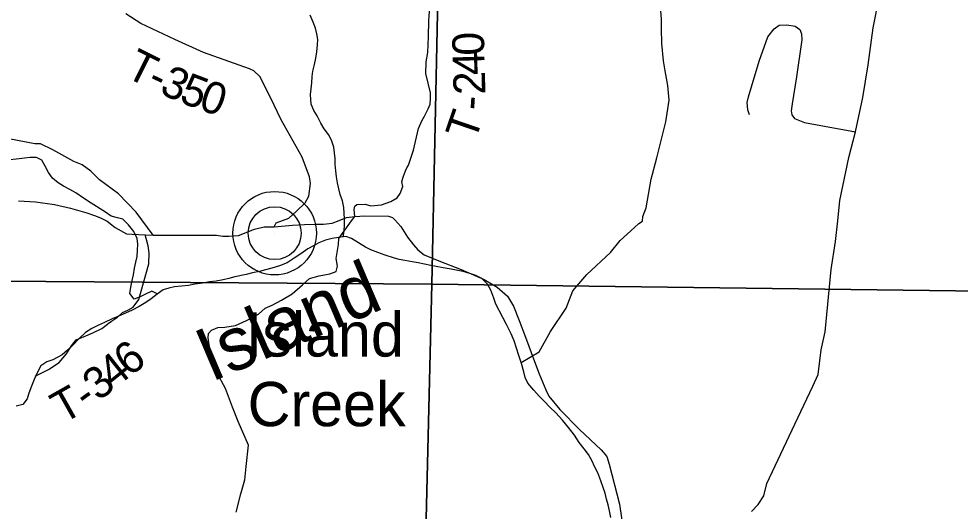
# Model space of a CAD drawing. Extents: x 2.1 to 8.9, y 14.1 to 20.9.
# Drawn here: x 3.78 to 5.459, y 17.71 to 18.588 of the extents above; entities that cross this region are included whole.
import ezdxf

# ---------------------------------------------------------------- set-up
doc = ezdxf.new("R2010")
doc.units = 0
for name, color, linetype in [('GM_X_City_Street', 7, 'Continuous'), ('GM_X_Interchange_Ramps', 7, 'Continuous'), ('GM_X_Major_River', 7, 'Continuous'), ('GM_X_Minor_River_Text', 7, 'Continuous'), ('GM_X_Rail_Line_Text', 7, 'Continuous'), ('GM_X_State_Route', 7, 'Continuous'), ('GM_X_State_Shield', 7, 'Continuous'), ('GM_X_Township_Text', 7, 'Continuous'), ('PV_P_Text', 7, 'Continuous'), ('TX_P_Misc', 7, 'Continuous')]:
    doc.layers.add(name, color=color, linetype=linetype)

msp = doc.modelspace()

# ---------------------------------------------------------------- linework, layer by layer
at = {"layer": 'GM_X_City_Street'}
for p, q in [((4.5117, 18.5848), (4.5132, 18.6095)), ((3.998, 18.5798), (3.9711, 18.5969)), ((4.511, 18.5565), (4.5117, 18.5848)), ((4.0586, 18.5514), (3.998, 18.5798)), ((5.1159, 18.5561), (5.127, 18.5706)), ((5.127, 18.5706), (5.1361, 18.5771)), ((5.1361, 18.5771), (5.1498, 18.5777)), ((5.1498, 18.5777), (5.1648, 18.5751)), ((5.1648, 18.5751), (5.1727, 18.5693)), ((5.1727, 18.5693), (5.176, 18.5614)), ((4.1098, 18.528), (4.0586, 18.5514)), ((4.5096, 18.5279), (4.511, 18.5565)), ((5.1005, 18.513), (5.1159, 18.5561)), ((5.1764, 18.5506), (5.1669, 18.4846)), ((5.176, 18.5614), (5.1764, 18.5506)), ((4.1918, 18.4988), (4.1098, 18.528)), ((4.5066, 18.5113), (4.5096, 18.5279)), ((4.1994, 18.4957), (4.1918, 18.4988)), ((4.5062, 18.4909), (4.5066, 18.5113)), ((5.0813, 18.4489), (5.1005, 18.513)), ((4.2099, 18.4854), (4.1994, 18.4957)), ((4.2293, 18.448), (4.2099, 18.4854)), ((4.5145, 18.4565), (4.5062, 18.4909)), ((5.1669, 18.4846), (5.1594, 18.4364)), ((4.248, 18.4081), (4.2293, 18.448)), ((4.5145, 18.4459), (4.5145, 18.4565)), ((5.079, 18.4391), (5.0813, 18.4489)), ((4.51, 18.4275), (4.5137, 18.4362)), ((4.5137, 18.4362), (4.5145, 18.4459)), ((5.0801, 18.4258), (5.079, 18.4391)), ((5.1594, 18.4364), (5.1573, 18.4243)), ((4.4987, 18.4065), (4.5038, 18.4148)), ((4.5038, 18.4148), (4.51, 18.4275)), ((5.0832, 18.4173), (5.0801, 18.4258)), ((5.1573, 18.4243), (5.1589, 18.417)), ((5.1589, 18.417), (5.1634, 18.4106)), ((4.2856, 18.3417), (4.248, 18.4081)), ((4.4932, 18.3927), (4.4987, 18.4065)), ((5.1634, 18.4106), (5.1812, 18.4035)), ((5.1812, 18.4035), (5.2104, 18.3982)), ((5.2104, 18.3982), (5.2723, 18.3867)), ((4.4843, 18.3542), (4.4932, 18.3927)), ((3.8087, 18.3652), (3.7467, 18.3772)), ((3.819, 18.3653), (3.8087, 18.3652)), ((3.8412, 18.3549), (3.819, 18.3653)), ((3.8785, 18.3341), (3.8412, 18.3549)), ((4.4752, 18.3275), (4.4843, 18.3542)), ((3.8935, 18.3278), (3.8785, 18.3341)), ((4.2987, 18.3066), (4.2856, 18.3417)), ((3.9085, 18.3166), (3.8935, 18.3278)), ((3.9244, 18.3011), (3.9085, 18.3166)), ((4.4662, 18.3076), (4.4697, 18.3172)), ((4.4697, 18.3172), (4.4724, 18.3223)), ((4.4724, 18.3223), (4.4752, 18.3275)), ((3.9579, 18.2762), (3.9244, 18.3011)), ((4.3005, 18.2947), (4.2987, 18.3066)), ((4.4634, 18.2975), (4.4652, 18.3039)), ((4.4652, 18.2892), (4.4634, 18.2975)), ((4.4652, 18.3039), (4.4662, 18.3076)), ((4.2973, 18.2717), (4.3005, 18.2947)), ((4.4601, 18.2768), (4.4652, 18.2892)), ((3.9894, 18.2433), (3.9579, 18.2762)), ((4.2911, 18.2603), (4.2973, 18.2717)), ((4.4271, 18.2566), (4.4439, 18.2622)), ((4.4439, 18.2622), (4.4547, 18.2693)), ((4.4547, 18.2693), (4.4601, 18.2768)), ((4.2619, 18.2327), (4.2757, 18.2454)), ((4.2757, 18.2454), (4.2911, 18.2603)), ((4.3786, 18.2483), (4.3794, 18.2541)), ((4.3793, 18.236), (4.3786, 18.2483)), ((4.3794, 18.2541), (4.3832, 18.2574)), ((4.3832, 18.2574), (4.398, 18.258)), ((4.398, 18.258), (4.4079, 18.2545)), ((4.4079, 18.2545), (4.4271, 18.2566)), ((4.0199, 18.2026), (3.9894, 18.2433)), ((4.2392, 18.2242), (4.2619, 18.2327)), ((4.3737, 18.2283), (4.3793, 18.236)), ((4.2357, 18.2174), (4.2392, 18.2242)), ((4.351, 18.1968), (4.3737, 18.2283)), ((4.0058, 18.2033), (4.0199, 18.2026)), ((4.0111, 18.1837), (4.0058, 18.2033)), ((4.3506, 18.1861), (4.351, 18.1968)), ((4.0125, 18.1707), (4.0111, 18.1837)), ((4.3463, 18.1607), (4.3506, 18.1861)), ((4.0121, 18.1516), (4.0125, 18.1707)), ((3.9943, 18.0877), (4.0121, 18.1516)), ((4.3461, 18.1378), (4.3484, 18.1471)), ((4.3484, 18.1471), (4.3463, 18.1607)), ((4.2989, 18.1253), (4.316, 18.1297)), ((4.316, 18.1297), (4.335, 18.1337)), ((4.335, 18.1337), (4.3461, 18.1378)), ((4.2675, 18.0977), (4.286, 18.1139)), ((4.286, 18.1139), (4.2989, 18.1253)), ((4.249, 18.0865), (4.2675, 18.0977)), ((3.9844, 18.074), (3.9943, 18.0877)), ((4.2198, 18.0723), (4.232, 18.0778)), ((4.232, 18.0778), (4.249, 18.0865)), ((3.9564, 18.0564), (3.9655, 18.0648)), ((3.9655, 18.0648), (3.9748, 18.0686)), ((3.9748, 18.0686), (3.9844, 18.074)), ((4.1861, 18.0504), (4.2078, 18.0613)), ((4.2078, 18.0613), (4.2198, 18.0723)), ((3.9382, 18.0435), (3.9399, 18.0447)), ((3.9399, 18.0447), (3.9457, 18.0491)), ((3.9457, 18.0491), (3.9564, 18.0564)), ((4.167, 18.0412), (4.1861, 18.0504)), ((3.9, 18.0231), (3.9122, 18.0282)), ((3.9122, 18.0282), (3.9282, 18.0361)), ((3.9282, 18.0361), (3.9382, 18.0435)), ((4.1185, 18.0269), (4.1241, 18.0333)), ((4.1241, 18.0333), (4.1355, 18.038)), ((4.1355, 18.038), (4.1479, 18.0386)), ((4.1479, 18.0386), (4.167, 18.0412)), ((3.8743, 18.0049), (3.8829, 18.0159)), ((3.8829, 18.0159), (3.9, 18.0231)), ((4.1181, 18.0195), (4.1185, 18.0269)), ((4.12, 18.0067), (4.1181, 18.0195)), ((3.8651, 17.9911), (3.8743, 18.0049)), ((4.1232, 17.9868), (4.12, 18.0067)), ((3.8525, 17.9754), (3.8651, 17.9911)), ((4.1338, 17.9561), (4.1232, 17.9868)), ((3.8097, 17.9511), (3.833, 17.9631)), ((3.833, 17.9631), (3.8525, 17.9754)), ((4.1487, 17.9291), (4.1338, 17.9561)), ((4.1615, 17.8955), (4.1487, 17.9291)), ((4.1713, 17.87), (4.1615, 17.8955)), ((4.1898, 17.828), (4.1713, 17.87)), ((4.1859, 17.7899), (4.1898, 17.828)), ((4.1835, 17.766), (4.1859, 17.7899)), ((4.176, 17.7412), (4.1835, 17.766)), ((4.1678, 17.7086), (4.176, 17.7412))]:
    msp.add_line(p, q, dxfattribs=at)
at = {"layer": 'GM_X_Interchange_Ramps'}
for p, q in [((4.5388, 19.1444), (4.5166, 18.1148)), ((4.5166, 18.1148), (4.5388, 19.1444)), ((4.5166, 18.1148), (3.5154, 18.1224)), ((3.5154, 18.1224), (4.5166, 18.1148)), ((4.5166, 18.1148), (4.4928, 17.1099)), ((4.4928, 17.1099), (4.5166, 18.1148)), ((5.5198, 18.1024), (4.5166, 18.1148)), ((4.5166, 18.1148), (5.5198, 18.1024))]:
    msp.add_line(p, q, dxfattribs=at)
at = {"layer": 'GM_X_Rail_Line_Text'}
for p, q in [((5.304, 18.5723), (5.3153, 18.63)), ((5.295, 18.506), (5.304, 18.5723)), ((5.2855, 18.4482), (5.295, 18.506)), ((5.2723, 18.3867), (5.2855, 18.4482)), ((5.2605, 18.341), (5.2723, 18.3867)), ((5.2444, 18.2642), (5.2605, 18.341)), ((5.2405, 18.2281), (5.2444, 18.2642)), ((5.2364, 18.1911), (5.2405, 18.2281)), ((5.2291, 18.1413), (5.2364, 18.1911)), ((5.2181, 18.0301), (5.2291, 18.1413)), ((5.2108, 17.9979), (5.2181, 18.0301)), ((5.2057, 17.9541), (5.2108, 17.9979)), ((5.1962, 17.9332), (5.2057, 17.9541)), ((5.1643, 17.8652), (5.1962, 17.9332)), ((5.114, 17.7597), (5.1643, 17.8652)), ((5.1088, 17.7379), (5.114, 17.7597)), ((5.0989, 17.7224), (5.1088, 17.7379)), ((5.0867, 17.7098), (5.0989, 17.7224))]:
    msp.add_line(p, q, dxfattribs=at)
at = {"layer": 'GM_X_State_Route'}
for radius in [0.0744, 0.0472]:
    msp.add_circle((4.2366, 18.206), radius, dxfattribs=at)
at = {"layer": 'GM_X_State_Shield'}
for p, q in [((3.78, 18.2638), (3.8103, 18.2619)), ((3.8103, 18.2619), (3.844, 18.257)), ((3.844, 18.257), (3.8725, 18.2504)), ((3.8725, 18.2504), (3.9015, 18.2423)), ((3.9015, 18.2423), (3.9152, 18.2378)), ((3.9152, 18.2378), (3.926, 18.2332)), ((3.926, 18.2332), (3.9378, 18.2276)), ((4.3389, 18.2238), (4.3516, 18.2287)), ((4.3516, 18.2287), (4.3644, 18.234)), ((4.3644, 18.234), (4.3793, 18.236)), ((4.3793, 18.236), (4.3975, 18.2368)), ((4.3975, 18.2368), (4.4395, 18.2365)), ((4.4395, 18.2365), (4.4464, 18.2337)), ((4.4464, 18.2337), (4.451, 18.2295)), ((4.451, 18.2295), (4.4613, 18.2179)), ((3.9378, 18.2276), (3.9522, 18.2163)), ((3.9522, 18.2163), (3.9726, 18.2051)), ((4.1721, 18.2019), (4.2007, 18.2129)), ((4.2007, 18.2129), (4.2178, 18.2175)), ((4.2178, 18.2175), (4.2357, 18.2174)), ((4.2357, 18.2174), (4.2681, 18.2202)), ((4.2681, 18.2202), (4.2897, 18.2213)), ((4.2897, 18.2213), (4.3089, 18.222)), ((4.3089, 18.222), (4.3239, 18.2223)), ((4.3239, 18.2223), (4.3389, 18.2238)), ((4.4613, 18.2179), (4.4735, 18.1991)), ((3.9726, 18.2051), (3.9822, 18.2041)), ((3.9822, 18.2041), (4.0058, 18.2033)), ((4.0058, 18.2033), (4.0199, 18.2026)), ((4.0199, 18.2026), (4.1326, 18.2027)), ((4.1326, 18.2027), (4.1441, 18.2008)), ((4.1441, 18.2008), (4.155, 18.2004)), ((4.155, 18.2004), (4.1721, 18.2019)), ((4.4735, 18.1991), (4.484, 18.1851)), ((4.484, 18.1851), (4.4919, 18.176)), ((4.4919, 18.176), (4.5034, 18.1673)), ((4.5034, 18.1673), (4.5292, 18.1568)), ((4.5292, 18.1568), (4.5694, 18.1412)), ((4.5694, 18.1412), (4.6101, 18.1236)), ((4.6101, 18.1236), (4.6334, 18.11)), ((4.6334, 18.11), (4.6516, 18.0936)), ((4.6516, 18.0936), (4.6626, 18.0758)), ((4.6626, 18.0758), (4.6725, 18.0501)), ((4.6725, 18.0501), (4.684, 18.0203)), ((4.684, 18.0203), (4.6996, 17.9772)), ((4.6996, 17.9772), (4.7079, 17.9554)), ((4.7079, 17.9554), (4.7198, 17.9268)), ((4.7198, 17.9268), (4.7257, 17.9155)), ((4.7257, 17.9155), (4.7453, 17.8914)), ((4.7453, 17.8914), (4.78, 17.8558)), ((4.78, 17.8558), (4.8188, 17.8199)), ((4.8188, 17.8199), (4.8287, 17.8076)), ((4.8287, 17.8076), (4.833, 17.7942)), ((4.833, 17.7942), (4.8512, 17.7226)), ((4.8512, 17.7226), (4.8578, 17.6782))]:
    msp.add_line(p, q, dxfattribs=at)
at = {"layer": 'GM_X_Township_Text'}
msp.add_line((4.2366, 18.206), (4.2366, 18.206), dxfattribs=at)
at = {"layer": 'TX_P_Misc'}
for p, q in [((4.9261, 18.5876), (4.923, 18.6343)), ((4.3051, 18.5825), (4.2998, 18.5945)), ((4.3092, 18.5716), (4.3051, 18.5825)), ((4.9264, 18.5701), (4.9261, 18.5876)), ((4.3118, 18.5614), (4.3092, 18.5716)), ((4.9272, 18.5442), (4.9264, 18.5701)), ((4.3137, 18.5516), (4.3118, 18.5614)), ((4.3132, 18.542), (4.3137, 18.5516)), ((4.3117, 18.5291), (4.3132, 18.542)), ((4.9296, 18.5131), (4.9272, 18.5442)), ((4.3075, 18.5065), (4.3098, 18.518)), ((4.3098, 18.518), (4.3117, 18.5291)), ((4.3048, 18.4946), (4.3075, 18.5065)), ((4.9326, 18.4953), (4.9296, 18.5131)), ((4.3031, 18.474), (4.3036, 18.4851)), ((4.3036, 18.4851), (4.3048, 18.4946)), ((4.9376, 18.4691), (4.9326, 18.4953)), ((4.3016, 18.4633), (4.3031, 18.474)), ((4.9399, 18.4433), (4.9376, 18.4691)), ((4.3004, 18.453), (4.3016, 18.4633)), ((4.3017, 18.4363), (4.3004, 18.453)), ((4.3062, 18.425), (4.3017, 18.4363)), ((4.9342, 18.4044), (4.9399, 18.4433)), ((4.3122, 18.415), (4.3062, 18.425)), ((4.3191, 18.4022), (4.3122, 18.415)), ((4.3251, 18.3921), (4.3191, 18.4022)), ((4.9179, 18.3403), (4.9342, 18.4044)), ((4.3323, 18.3817), (4.3251, 18.3921)), ((4.3379, 18.3716), (4.3323, 18.3817)), ((4.3421, 18.3596), (4.3379, 18.3716)), ((4.3431, 18.3493), (4.3421, 18.3596)), ((4.3442, 18.3391), (4.3431, 18.3493)), ((3.7808, 18.3386), (3.7588, 18.3363)), ((3.7906, 18.34), (3.7808, 18.3386)), ((3.8005, 18.3411), (3.7906, 18.34)), ((3.8119, 18.3407), (3.8005, 18.3411)), ((3.8215, 18.3364), (3.8119, 18.3407)), ((3.8276, 18.3256), (3.8215, 18.3364)), ((4.3445, 18.3288), (4.3442, 18.3391)), ((4.908, 18.3024), (4.9179, 18.3403)), ((3.8332, 18.3139), (3.8276, 18.3256)), ((3.8404, 18.3039), (3.8332, 18.3139)), ((4.3457, 18.3171), (4.3445, 18.3288)), ((4.3468, 18.3065), (4.3457, 18.3171)), ((3.8505, 18.2958), (3.8404, 18.3039)), ((3.8602, 18.2897), (3.8505, 18.2958)), ((4.3486, 18.2955), (4.3468, 18.3065)), ((4.8987, 18.2513), (4.908, 18.3024)), ((3.8714, 18.2839), (3.8602, 18.2897)), ((3.8823, 18.2782), (3.8714, 18.2839)), ((4.3508, 18.2853), (4.3486, 18.2955)), ((4.3534, 18.2751), (4.3508, 18.2853)), ((3.8959, 18.2687), (3.8823, 18.2782)), ((3.9091, 18.2593), (3.8959, 18.2687)), ((4.3576, 18.2634), (4.3534, 18.2751)), ((4.3599, 18.2517), (4.3576, 18.2634)), ((3.9347, 18.2433), (3.9091, 18.2593)), ((4.3606, 18.2415), (4.3599, 18.2517)), ((4.8929, 18.236), (4.8987, 18.2513)), ((3.9451, 18.2364), (3.9347, 18.2433)), ((3.9563, 18.2333), (3.9451, 18.2364)), ((3.9658, 18.231), (3.9563, 18.2333)), ((3.976, 18.221), (3.9658, 18.231)), ((4.3609, 18.2316), (4.3606, 18.2415)), ((4.3608, 18.2213), (4.3609, 18.2316)), ((4.8927, 18.2273), (4.8929, 18.236)), ((3.9852, 18.2087), (3.976, 18.221)), ((4.3604, 18.2095), (4.3608, 18.2213)), ((4.8528, 18.1927), (4.8781, 18.216)), ((4.8781, 18.216), (4.8859, 18.2233)), ((4.8859, 18.2233), (4.8927, 18.2273)), ((3.9916, 18.1968), (3.9852, 18.2087)), ((3.9927, 18.1862), (3.9916, 18.1968)), ((4.3391, 18.1963), (4.3271, 18.1936)), ((4.3501, 18.1981), (4.3391, 18.1963)), ((4.3634, 18.2001), (4.3501, 18.1981)), ((4.3586, 18.1994), (4.3604, 18.2095)), ((4.3737, 18.1966), (4.3634, 18.2001)), ((4.3861, 18.189), (4.3737, 18.1966)), ((3.9919, 18.1755), (3.9927, 18.1862)), ((4.3057, 18.1834), (4.2956, 18.1778)), ((4.3154, 18.1887), (4.3057, 18.1834)), ((4.3271, 18.1936), (4.3154, 18.1887)), ((4.3986, 18.181), (4.3861, 18.189)), ((4.4082, 18.1764), (4.3986, 18.181)), ((4.8354, 18.1715), (4.8528, 18.1927)), ((3.9891, 18.1545), (3.9911, 18.1644)), ((3.9911, 18.1644), (3.9919, 18.1755)), ((4.2714, 18.1614), (4.2591, 18.1534)), ((4.2833, 18.169), (4.2714, 18.1614)), ((4.2956, 18.1778), (4.2833, 18.169)), ((4.4205, 18.1718), (4.4082, 18.1764)), ((4.4336, 18.1665), (4.4205, 18.1718)), ((4.4482, 18.162), (4.4336, 18.1665)), ((4.4585, 18.1589), (4.4482, 18.162)), ((4.7934, 18.1324), (4.8354, 18.1715)), ((3.9868, 18.1434), (3.9891, 18.1545)), ((4.2452, 18.1477), (4.2313, 18.1434)), ((4.2591, 18.1534), (4.2452, 18.1477)), ((4.4689, 18.157), (4.4585, 18.1589)), ((4.4815, 18.1551), (4.4689, 18.157)), ((4.4922, 18.1531), (4.4815, 18.1551)), ((4.504, 18.1508), (4.4922, 18.1531)), ((4.5148, 18.1485), (4.504, 18.1508)), ((4.5247, 18.1465), (4.5148, 18.1485)), ((4.5373, 18.1443), (4.5247, 18.1465)), ((3.9825, 18.1215), (3.9849, 18.1319)), ((3.9849, 18.1319), (3.9868, 18.1434)), ((4.1656, 18.128), (4.1547, 18.1254)), ((4.186, 18.1325), (4.1656, 18.128)), ((4.1973, 18.1351), (4.186, 18.1325)), ((4.2094, 18.1378), (4.1973, 18.1351)), ((4.2203, 18.1404), (4.2094, 18.1378)), ((4.2313, 18.1434), (4.2203, 18.1404)), ((4.5511, 18.142), (4.5373, 18.1443)), ((4.563, 18.1394), (4.5511, 18.142)), ((4.5729, 18.1374), (4.563, 18.1394)), ((4.5848, 18.134), (4.5729, 18.1374)), ((4.5952, 18.1305), (4.5848, 18.134)), ((4.606, 18.1251), (4.5952, 18.1305)), ((4.7682, 18.1031), (4.7934, 18.1324)), ((3.9802, 18.11), (3.9825, 18.1215)), ((4.0703, 18.1117), (4.0582, 18.1106)), ((4.0828, 18.1129), (4.0703, 18.1117)), ((4.0945, 18.1148), (4.0828, 18.1129)), ((4.1082, 18.1167), (4.0945, 18.1148)), ((4.1206, 18.119), (4.1082, 18.1167)), ((4.1324, 18.1205), (4.1206, 18.119)), ((4.1449, 18.1228), (4.1324, 18.1205)), ((4.1547, 18.1254), (4.1449, 18.1228)), ((4.6162, 18.1148), (4.606, 18.1251)), ((4.6222, 18.1043), (4.6162, 18.1148)), ((3.9783, 18.0986), (3.9802, 18.11)), ((3.9858, 18.0885), (3.9783, 18.0986)), ((4.0065, 18.0975), (3.9968, 18.0923)), ((4.0174, 18.1025), (4.0065, 18.0975)), ((4.027, 18.0974), (4.0162, 18.0891)), ((4.0273, 18.0976), (4.0174, 18.1025)), ((4.0378, 18.105), (4.027, 18.0974)), ((4.0476, 18.108), (4.0378, 18.105)), ((4.0582, 18.1106), (4.0476, 18.108)), ((4.6272, 18.0904), (4.6222, 18.1043)), ((4.7562, 18.0725), (4.7682, 18.1031)), ((3.9968, 18.0923), (3.9858, 18.0885)), ((4.0066, 18.0823), (3.995, 18.0755)), ((4.0162, 18.0891), (4.0066, 18.0823)), ((4.631, 18.0795), (4.6272, 18.0904)), ((4.6366, 18.0679), (4.631, 18.0795)), ((3.9703, 18.0633), (3.9572, 18.0572)), ((3.9823, 18.069), (3.9703, 18.0633)), ((3.995, 18.0755), (3.9823, 18.069)), ((4.65, 18.0432), (4.6366, 18.0679)), ((4.7286, 18.0309), (4.7562, 18.0725)), ((3.9332, 18.0465), (3.9227, 18.042)), ((3.947, 18.0531), (3.9332, 18.0465)), ((3.9572, 18.0572), (3.947, 18.0531)), ((3.8991, 18.0291), (3.8877, 18.0181)), ((3.9103, 18.0363), (3.8991, 18.0291)), ((3.9227, 18.042), (3.9103, 18.0363)), ((4.6581, 18.0267), (4.65, 18.0432)), ((4.7081, 17.9944), (4.7286, 18.0309)), ((3.8877, 18.0181), (3.8766, 18.0063)), ((4.6634, 18.0139), (4.6581, 18.0267)), ((4.6676, 18.0011), (4.6634, 18.0139)), ((3.867, 17.9973), (3.8574, 17.989)), ((3.8766, 18.0063), (3.867, 17.9973)), ((4.6722, 17.9879), (4.6676, 18.0011)), ((4.6762, 17.9756), (4.7081, 17.9944)), ((3.8304, 17.9767), (3.8196, 17.9692)), ((3.8409, 17.9801), (3.8304, 17.9767)), ((3.8574, 17.989), (3.8409, 17.9801)), ((4.6768, 17.9736), (4.6722, 17.9879)), ((3.8196, 17.9692), (3.8131, 17.9568)), ((4.6811, 17.9585), (4.6768, 17.9736)), ((3.8078, 17.9452), (3.8028, 17.9329)), ((3.8131, 17.9568), (3.8078, 17.9452)), ((4.6833, 17.9487), (4.6811, 17.9585)), ((4.6882, 17.9386), (4.6833, 17.9487)), ((3.8028, 17.9329), (3.7983, 17.9209)), ((4.6984, 17.9263), (4.6882, 17.9386)), ((3.7952, 17.9109), (3.7875, 17.9004)), ((3.7983, 17.9209), (3.7952, 17.9109)), ((4.7083, 17.9152), (4.6984, 17.9263)), ((4.7177, 17.9056), (4.7083, 17.9152)), ((3.7875, 17.9004), (3.7758, 17.8978)), ((4.7271, 17.8956), (4.7177, 17.9056)), ((4.7381, 17.8857), (4.7271, 17.8956)), ((4.7499, 17.8724), (4.7381, 17.8857)), ((4.7606, 17.8594), (4.7499, 17.8724)), ((4.7709, 17.8456), (4.7606, 17.8594)), ((4.7793, 17.8326), (4.7709, 17.8456)), ((4.7887, 17.8215), (4.7793, 17.8326)), ((4.7959, 17.8114), (4.7887, 17.8215)), ((4.8023, 17.8009), (4.7959, 17.8114)), ((4.8076, 17.7889), (4.8023, 17.8009)), ((4.8129, 17.7784), (4.8076, 17.7889)), ((4.8179, 17.7641), (4.8129, 17.7784)), ((4.8224, 17.7525), (4.8179, 17.7641)), ((4.8258, 17.7423), (4.8224, 17.7525)), ((4.8284, 17.7317), (4.8258, 17.7423)), ((4.831, 17.7215), (4.8284, 17.7317)), ((4.8336, 17.7106), (4.831, 17.7215)), ((4.8359, 17.6988), (4.8336, 17.7106))]:
    msp.add_line(p, q, dxfattribs=at)

# ---------------------------------------------------------------- texts
at = {"layer": 'GM_X_Major_River'}
for s, p in [('Island', (4.1851, 17.986)), ('Creek', (4.1884, 17.8618))]:
    msp.add_text(s, height=0.07898, rotation=0, dxfattribs=at).set_placement(p)
at = {"layer": 'GM_X_Minor_River_Text'}
for s, rotation, p in [('0', 91.0721, (4.6105, 18.5232)), ('T', 333.5749, (3.9677, 18.4861)), ('4', 91.6364, (4.6115, 18.4883)), ('3', 335.8451, (4.029, 18.4561)), ('-', 334.526, (4.0066, 18.4667)), ('5', 339.251, (4.0643, 18.4404)), ('2', 91.5723, (4.6125, 18.4533)), ('0', 340.9478, (4.0988, 18.4274)), ('-', 86.1417, (4.6108, 18.4241)), ('T', 71.0839, (4.5938, 18.368)), ('6', 37.3788, (3.9773, 17.9488)), ('4', 38.6208, (3.9503, 17.9271)), ('3', 38.6367, (3.9229, 17.9053)), ('T', 29.418, (3.8587, 17.8651)), ('-', 35.8589, (3.9016, 17.8898))]:
    msp.add_text(s, height=0.0568, rotation=rotation, dxfattribs=at).set_placement(p)
at = {"layer": 'PV_P_Text'}
msp.add_text('Island', height=0.09472, rotation=23.1154, dxfattribs=at).set_placement((4.1229, 17.9398))

doc.saveas('drawing.dxf')
